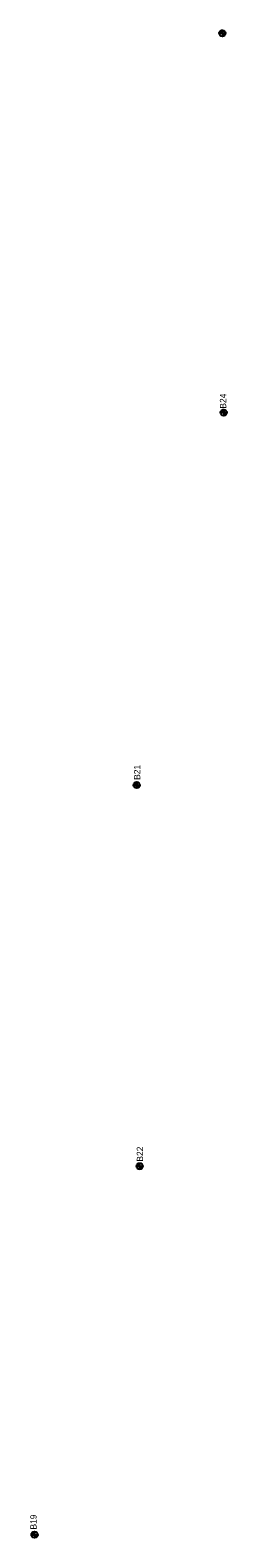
# Model space of a CAD drawing. Extents: x 311409 to 379449, y 121539 to 224848.
# Drawn here: x 361288 to 361600, y 139155 to 141546 of the extents above; entities that cross this region are included whole.
import ezdxf

# ---------------------------------------------------------------- set-up
doc = ezdxf.new("R2010")
doc.units = 0
for name, color, linetype in [('E_SOIL_BORE1 [KAPUR_CADDS_LEVELS]', 7, 'Continuous'), ('E_SOIL_BORE2 [KAPUR_CADDS_LEVELS]', 7, 'Continuous'), ('P_MARK', 7, 'Continuous')]:
    doc.layers.add(name, color=color, linetype=linetype)

msp = doc.modelspace()

# ---------------------------------------------------------------- linework, layer by layer
at = {"layer": 'P_MARK'}
for p, q in [((361588.1, 141541), (361598.1, 141541)), ((361593.1, 141546), (361593.1, 141536)), ((361595.2, 140944.3), (361595.2, 140934.4)), ((361590.2, 140939.4), (361600.2, 140939.3)), ((361452.1, 140348.7), (361462, 140348.7)), ((361457.1, 140353.7), (361457, 140343.7)), ((361456.7, 139744.2), (361466.7, 139744.2)), ((361461.7, 139749.2), (361461.7, 139739.2)), ((361289.9, 139159.7), (361299.9, 139159.7)), ((361294.9, 139164.7), (361294.9, 139154.7))]:
    msp.add_line(p, q, dxfattribs=at)
for centre in [(361593.1, 141541), (361595.2, 140939.4), (361457.1, 140348.7), (361461.7, 139744.2), (361294.9, 139159.7)]:
    msp.add_circle(centre, 5, dxfattribs=at)
for centre, radius, start, end in [((361593.1, 141541), 4.5, 89.9869, 179.9869), ((361593.1, 141541), 4, 89.9869, 179.9869), ((361593.1, 141541), 3.5, 89.9869, 179.9869), ((361593.1, 141541), 3, 89.9869, 179.9869), ((361593.1, 141541), 2.5, 89.9869, 179.9869), ((361593.1, 141541), 2, 89.9869, 179.9869), ((361593.1, 141541), 1.5, 89.9869, 179.9869), ((361593.1, 141541), 1, 89.9869, 179.9869), ((361593.1, 141541), 0.5, 89.9869, 179.9869), ((361593.1, 141541), 4.5, 269.9869, 359.9869), ((361593.1, 141541), 4, 269.9869, 359.9869), ((361593.1, 141541), 3.5, 269.9869, 359.9869), ((361593.1, 141541), 3, 269.9869, 359.9869), ((361593.1, 141541), 2.5, 269.9869, 359.9869), ((361593.1, 141541), 2, 269.9869, 359.9869), ((361593.1, 141541), 1.5, 269.9869, 359.9869), ((361593.1, 141541), 1, 269.9869, 359.9869), ((361593.1, 141541), 0.5, 269.9869, 359.9869), ((361595.2, 140939.4), 4.5, 89.9869, 179.9869), ((361595.2, 140939.4), 4, 89.9869, 179.9869), ((361595.2, 140939.4), 3.5, 89.9869, 179.9869), ((361595.2, 140939.4), 3, 89.9869, 179.9869), ((361595.2, 140939.4), 2.5, 89.9869, 179.9869), ((361595.2, 140939.4), 2, 89.9869, 179.9869), ((361595.2, 140939.4), 1.5, 89.9869, 179.9869), ((361595.2, 140939.4), 1, 89.9869, 179.9869), ((361595.2, 140939.4), 0.5, 89.9869, 179.9869), ((361595.2, 140939.4), 4.5, 269.9869, 359.9869), ((361595.2, 140939.4), 4, 269.9869, 359.9869), ((361595.2, 140939.4), 3.5, 269.9869, 359.9869), ((361595.2, 140939.4), 3, 269.9869, 359.9869), ((361595.2, 140939.4), 2.5, 269.9869, 359.9869), ((361595.2, 140939.4), 2, 269.9869, 359.9869), ((361595.2, 140939.4), 1.5, 269.9869, 359.9869), ((361595.2, 140939.4), 1, 269.9869, 359.9869), ((361595.2, 140939.4), 0.5, 269.9869, 359.9869), ((361457.1, 140348.7), 4.5, 89.9869, 179.9869), ((361457.1, 140348.7), 4, 89.9869, 179.9869), ((361457.1, 140348.7), 3.5, 89.9869, 179.9869), ((361457.1, 140348.7), 3, 89.9869, 179.9869), ((361457.1, 140348.7), 2.5, 89.9869, 179.9869), ((361457.1, 140348.7), 2, 89.9869, 179.9869), ((361457.1, 140348.7), 1.5, 89.9869, 179.9869), ((361457.1, 140348.7), 1, 89.9869, 179.9869), ((361457.1, 140348.7), 0.5, 89.9869, 179.9869), ((361457.1, 140348.7), 4.5, 269.9869, 359.9869), ((361457.1, 140348.7), 4, 269.9869, 359.9869), ((361457.1, 140348.7), 3.5, 269.9869, 359.9869), ((361457.1, 140348.7), 3, 269.9869, 359.9869), ((361457.1, 140348.7), 2.5, 269.9869, 359.9869), ((361457.1, 140348.7), 2, 269.9869, 359.9869), ((361457.1, 140348.7), 1.5, 269.9869, 359.9869), ((361457.1, 140348.7), 1, 269.9869, 359.9869), ((361457.1, 140348.7), 0.5, 269.9869, 359.9869), ((361461.7, 139744.2), 4.5, 89.9869, 179.9869), ((361461.7, 139744.2), 4, 89.9869, 179.9869), ((361461.7, 139744.2), 3.5, 89.9869, 179.9869), ((361461.7, 139744.2), 3, 89.9869, 179.9869), ((361461.7, 139744.2), 2.5, 89.9869, 179.9869), ((361461.7, 139744.2), 2, 89.9869, 179.9869), ((361461.7, 139744.2), 1.5, 89.9869, 179.9869), ((361461.7, 139744.2), 1, 89.9869, 179.9869), ((361461.7, 139744.2), 0.5, 89.9869, 179.9869), ((361461.7, 139744.2), 4.5, 269.9869, 359.9869), ((361461.7, 139744.2), 4, 269.9869, 359.9869), ((361461.7, 139744.2), 3.5, 269.9869, 359.9869), ((361461.7, 139744.2), 3, 269.9869, 359.9869), ((361461.7, 139744.2), 2.5, 269.9869, 359.9869), ((361461.7, 139744.2), 2, 269.9869, 359.9869), ((361461.7, 139744.2), 1.5, 269.9869, 359.9869), ((361461.7, 139744.2), 1, 269.9869, 359.9869), ((361461.7, 139744.2), 0.5, 269.9869, 359.9869), ((361294.9, 139159.7), 4.5, 89.9869, 179.9869), ((361294.9, 139159.7), 4, 89.9869, 179.9869), ((361294.9, 139159.7), 3.5, 89.9869, 179.9869), ((361294.9, 139159.7), 3, 89.9869, 179.9869), ((361294.9, 139159.7), 2.5, 89.9869, 179.9869), ((361294.9, 139159.7), 2, 89.9869, 179.9869), ((361294.9, 139159.7), 1.5, 89.9869, 179.9869), ((361294.9, 139159.7), 1, 89.9869, 179.9869), ((361294.9, 139159.7), 0.5, 89.9869, 179.9869), ((361294.9, 139159.7), 4.5, 269.9869, 359.9869), ((361294.9, 139159.7), 4, 269.9869, 359.9869), ((361294.9, 139159.7), 3.5, 269.9869, 359.9869), ((361294.9, 139159.7), 3, 269.9869, 359.9869), ((361294.9, 139159.7), 2.5, 269.9869, 359.9869), ((361294.9, 139159.7), 2, 269.9869, 359.9869), ((361294.9, 139159.7), 1.5, 269.9869, 359.9869), ((361294.9, 139159.7), 1, 269.9869, 359.9869), ((361294.9, 139159.7), 0.5, 269.9869, 359.9869)]:
    msp.add_arc(centre, radius, start, end, dxfattribs=at)

# ---------------------------------------------------------------- texts
at = {"layer": 'E_SOIL_BORE1 [KAPUR_CADDS_LEVELS]'}
msp.add_text('B24', height=10, rotation=89.9869, dxfattribs=at).set_placement((361599.1, 140945.7))
at = {"layer": 'E_SOIL_BORE2 [KAPUR_CADDS_LEVELS]'}
for s, p in [('B21', (361462.7, 140356.9)), ('B22', (361467.2, 139751.4)), ('B19', (361298.1, 139167.9))]:
    msp.add_text(s, height=10, rotation=89.9869, dxfattribs=at).set_placement(p)

doc.saveas('drawing.dxf')
